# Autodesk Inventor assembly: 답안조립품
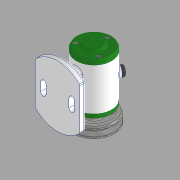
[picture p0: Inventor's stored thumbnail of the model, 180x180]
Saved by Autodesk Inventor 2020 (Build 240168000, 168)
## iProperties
Created: 2022-02
Part Number: 답안조립품
Document SubType Name: Assembly
Designer: 602-11
Author: 602-11
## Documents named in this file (14)
- C:\Users\602-11\Desktop\720206V1028\답안조립품.iam
- C:\Users\602-11\Desktop\720206V1028\본체.ipt
- C:\Users\602-11\Desktop\720206V1028\베어링 6002.ipt
- C:\Users\602-11\Desktop\720206V1028\축.ipt
- C:\Users\602-11\Desktop\720206V1028\뒤커버.ipt
- C:\Users\602-11\Desktop\720206V1028\앞커버.ipt
- C:\Users\602-11\Desktop\720206V1028\오일 실 15 x 25 x 7.ipt
- C:\Users\602-11\Desktop\720206V1028\키 3 x 3 x 12.ipt
- C:\Users\602-11\Desktop\720206V1028\V벨트풀리.ipt
- C:\Users\602-11\Desktop\720206V1028\고무 캡.ipt
- C:\Users\602-11\Desktop\720206V1028\평와셔 8 x 17.ipt
- C:\Users\602-11\Desktop\720206V1028\스프링와셔 8.ipt
- C:\Users\602-11\Desktop\720206V1028\너트 M8.ipt
- C:\Users\602-11\Desktop\720206V1028\볼트 M4 x 10.ipt
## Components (2 placed, 2 different names)
1. V벨트풀리:1
2. 고무 캡:1
